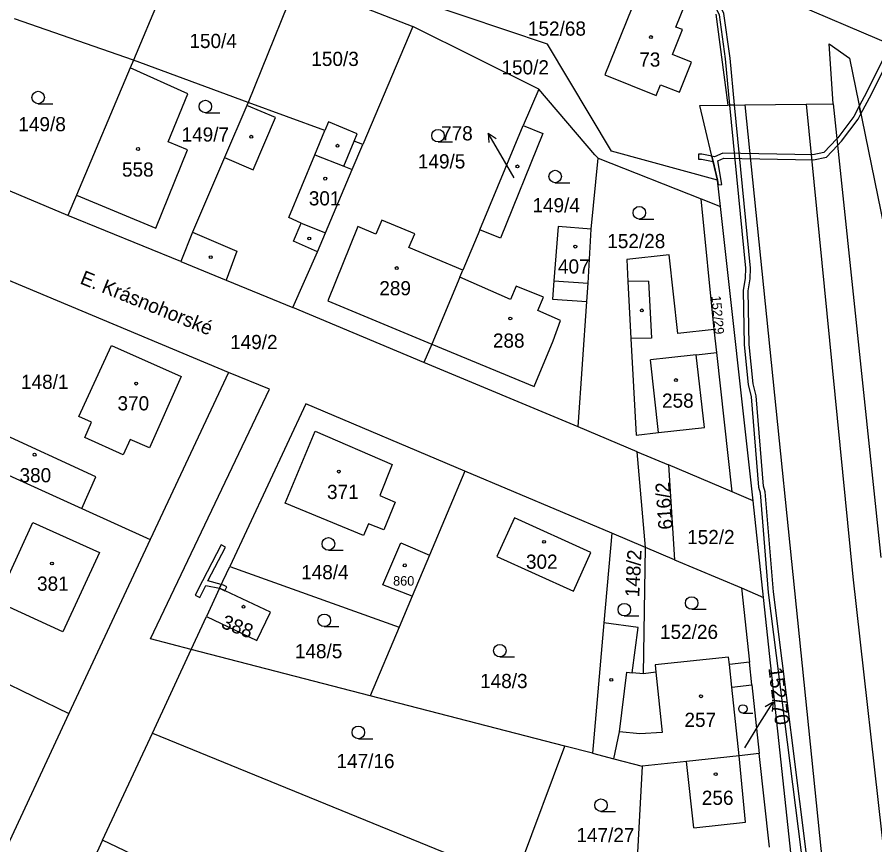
# Model space of a CAD drawing. Extents: x -783948 to -781889, y -1005870 to -1004430.
# Drawn here: x -783020.1 to -782917.3, y -1005140.8 to -1005041.6 of the extents above; entities that cross this region are included whole.
import ezdxf

# ---------------------------------------------------------------- set-up
doc = ezdxf.new("R2010")
doc.units = 0
for name, color, linetype in [('Vrstva 1', 7, 'Continuous'), ('Vrstva 13', 7, 'Continuous'), ('Vrstva 2', 7, 'Continuous'), ('Vrstva 3', 7, 'Continuous'), ('Vrstva 4', 7, 'Continuous'), ('Vrstva 5', 7, 'Continuous'), ('Vrstva 6', 7, 'Continuous'), ('Vrstva 7', 7, 'Continuous')]:
    doc.layers.add(name, color=color, linetype=linetype)

msp = doc.modelspace()

# ---------------------------------------------------------------- linework, layer by layer
at = {"layer": 'Vrstva 1'}
for p, q in [((-782999.94, -1005032.04), (-783006.14, -1005046.74)), ((-782986.5, -1005037.29), (-782972.67, -1005042.7)), ((-782987.66, -1005040.14), (-782992.39, -1005051.79)), ((-782936.33, -1005041.21), (-782934.89, -1005052.11)), ((-783006.14, -1005046.74), (-783020.39, -1005041.77)), ((-782972.67, -1005042.7), (-782978.65, -1005056.84)), ((-782957.57, -1005050.22), (-782972.67, -1005042.7)), ((-783006.51, -1005047.67), (-783012.96, -1005062.93)), ((-783006.14, -1005046.74), (-783006.51, -1005047.67)), ((-782999.61, -1005050.78), (-783006.51, -1005047.67)), ((-782992.39, -1005051.79), (-783006.14, -1005046.74)), ((-782957.57, -1005050.22), (-782959.43, -1005054.57)), ((-782922.29, -1005051.97), (-782916.56, -1005106.32)), ((-782979.31, -1005055.56), (-782982.78, -1005054.12)), ((-782964.62, -1005067.05), (-782959.43, -1005054.57)), ((-782959.43, -1005054.57), (-782957.07, -1005055.53)), ((-782957.07, -1005055.53), (-782962.16, -1005068.05)), ((-782951.29, -1005067), (-782950.45, -1005058.48)), ((-782950.45, -1005058.48), (-782938.09, -1005063.35)), ((-783013.98, -1005065.35), (-783027.87, -1005059.51)), ((-782935.79, -1005064.26), (-782936.14, -1005061.11)), ((-783012.96, -1005062.93), (-783013.98, -1005065.35)), ((-783012.96, -1005062.93), (-783003.45, -1005066.86)), ((-782938.09, -1005063.35), (-782935.79, -1005064.26)), ((-782936.55, -1005079.01), (-782938.09, -1005063.35)), ((-782931.85, -1005099.54), (-782935.79, -1005064.26)), ((-783000.45, -1005070.86), (-783013.98, -1005065.35)), ((-782964.62, -1005067.05), (-782966.68, -1005071.9)), ((-782962.16, -1005068.05), (-782964.62, -1005067.05)), ((-782951.29, -1005067), (-782955.25, -1005066.65)), ((-782951.64, -1005073.46), (-782951.29, -1005067)), ((-782966.68, -1005071.9), (-782973.12, -1005069.2)), ((-782967.02, -1005072.72), (-782966.68, -1005071.9)), ((-782994.76, -1005084.16), (-783021.91, -1005072.77)), ((-782967.02, -1005072.72), (-782970.39, -1005080.77)), ((-782960.94, -1005075.4), (-782967.02, -1005072.72)), ((-782951.79, -1005075.65), (-782951.64, -1005073.46)), ((-782971.34, -1005082.96), (-782987.02, -1005076.36)), ((-782982.85, -1005075.57), (-782970.39, -1005080.77)), ((-782952.82, -1005090.67), (-782951.79, -1005075.65)), ((-782936.24, -1005081.78), (-782936.55, -1005079.01)), ((-782970.39, -1005080.77), (-782971.34, -1005082.96)), ((-782934.38, -1005098.47), (-782936.24, -1005081.78)), ((-782952.82, -1005090.67), (-782971.34, -1005082.96)), ((-782994.76, -1005084.16), (-783004.12, -1005104.17)), ((-782945.78, -1005093.65), (-782952.82, -1005090.67)), ((-783010.64, -1005096.66), (-783022.7, -1005091.12)), ((-782945.78, -1005093.65), (-782942.02, -1005095.24)), ((-782944.78, -1005105.12), (-782945.78, -1005093.65)), ((-783024.44, -1005094.96), (-783012.33, -1005100.45)), ((-782966.41, -1005095.98), (-782970.66, -1005106.04)), ((-782948.82, -1005103.41), (-782966.41, -1005095.98)), ((-782934.38, -1005098.47), (-782942.02, -1005095.24)), ((-782942.02, -1005095.24), (-782941.29, -1005106.6)), ((-783012.33, -1005100.45), (-783010.64, -1005096.66)), ((-782931.85, -1005099.54), (-782934.38, -1005098.47)), ((-782930.61, -1005111.11), (-782931.85, -1005099.54)), ((-783012.33, -1005100.45), (-783004.12, -1005104.17)), ((-783004.12, -1005104.17), (-783013.87, -1005125.04)), ((-782948.82, -1005103.41), (-782949.77, -1005114.16)), ((-782944.78, -1005105.12), (-782948.82, -1005103.41)), ((-782944.99, -1005120.25), (-782944.78, -1005105.12)), ((-782941.29, -1005106.6), (-782944.78, -1005105.12)), ((-782970.66, -1005106.04), (-782972.74, -1005110.96)), ((-782941.29, -1005106.6), (-782933.28, -1005109.98)), ((-782995.82, -1005110), (-782994.6, -1005107.41)), ((-782994.6, -1005107.41), (-782974.31, -1005114.68)), ((-783044.29, -1005110.32), (-783013.87, -1005125.04)), ((-782995.82, -1005110), (-782997.38, -1005113.39)), ((-782989.73, -1005112.9), (-782995.82, -1005110)), ((-782933.28, -1005109.98), (-782930.61, -1005111.11)), ((-782933.28, -1005109.98), (-782932.32, -1005118.88)), ((-782972.74, -1005110.96), (-782974.31, -1005114.68)), ((-782914.35, -1005262.66), (-782930.61, -1005111.11)), ((-782999.22, -1005117.35), (-782997.38, -1005113.39)), ((-782997.38, -1005113.39), (-782991.34, -1005116.27)), ((-782991.34, -1005116.27), (-782989.73, -1005112.9)), ((-782949.77, -1005114.16), (-782951.14, -1005129.78)), ((-782945.66, -1005114.7), (-782949.77, -1005114.16)), ((-782974.31, -1005114.68), (-782977.78, -1005122.9)), ((-782946.36, -1005120.13), (-782945.66, -1005114.7)), ((-783003.87, -1005127.37), (-782999.22, -1005117.35)), ((-782977.78, -1005122.9), (-782999.22, -1005117.35)), ((-782934.81, -1005118.29), (-782943.63, -1005119.2)), ((-782932.03, -1005121.6), (-782932.32, -1005118.88)), ((-782944.99, -1005120.25), (-782946.36, -1005120.13)), ((-782932.03, -1005121.6), (-782931.14, -1005129.82)), ((-782954.45, -1005128.93), (-782977.78, -1005122.9)), ((-783013.87, -1005125.04), (-783023.28, -1005145.16)), ((-783009.84, -1005140.2), (-783003.87, -1005127.37)), ((-783003.87, -1005127.37), (-782960.46, -1005145.08)), ((-782960.46, -1005145.08), (-782954.45, -1005128.93)), ((-782951.14, -1005129.78), (-782954.45, -1005128.93)), ((-782931.14, -1005129.82), (-782933.54, -1005130.08)), ((-782929.92, -1005141.06), (-782931.14, -1005129.82)), ((-782945.15, -1005131.33), (-782946.27, -1005150.87)), ((-783009.84, -1005140.2), (-783017.65, -1005157)), ((-782947.58, -1005169.77), (-783009.84, -1005140.2))]:
    msp.add_line(p, q, dxfattribs=at)
for points in [[(-782936.14, -1005061.11), (-782948.86, -1005057.63), (-782956.51, -1005044.83), (-782971.51, -1005039.79)], [(-782943.48, -1005050.96), (-782942.96, -1005049.67), (-782940.7, -1005050.58), (-782939.25, -1005046.99), (-782941.54, -1005046.07), (-782940.33, -1005043.07), (-782941.12, -1005042.76), (-782939.93, -1005039.81)], [(-782946.4, -1005040.51), (-782949.63, -1005048.48), (-782943.48, -1005050.96)], [(-782922.29, -1005051.97), (-782922.75, -1005044.77), (-782920.33, -1005046.49), (-782913.56, -1005079.53)], [(-783003.45, -1005066.86), (-782999.67, -1005057.49), (-783001.99, -1005056.54), (-782999.61, -1005050.78)], [(-782950.45, -1005058.48), (-782950.85, -1005058.06), (-782957.57, -1005050.22)], [(-782992.39, -1005051.79), (-782992.55, -1005052.17), (-782995.23, -1005058.41), (-782999.06, -1005067.34), (-783000.45, -1005070.86)], [(-782982.78, -1005054.12), (-782983.21, -1005055.16), (-782992.39, -1005051.79)], [(-782936.14, -1005061.11), (-782938.26, -1005052.15), (-782934.89, -1005052.11)], [(-782934.89, -1005052.11), (-782932.86, -1005052.09), (-782925.51, -1005052.01), (-782922.29, -1005051.97)], [(-782978.65, -1005056.84), (-782979.68, -1005056.46), (-782979.31, -1005055.56)], [(-782987.02, -1005076.36), (-782984.09, -1005069.7), (-782983.13, -1005067.44), (-782979.92, -1005059.85), (-782978.65, -1005056.84)], [(-782973.12, -1005069.2), (-782972.43, -1005067.55), (-782976.38, -1005065.9), (-782977.08, -1005067.58), (-782979.23, -1005066.68), (-782982.85, -1005075.57)], [(-782955.25, -1005066.65), (-782955.76, -1005073.17), (-782955.93, -1005075.36), (-782951.79, -1005075.65)], [(-782936.55, -1005079.01), (-782940.89, -1005079.49), (-782941.94, -1005070.06), (-782947.02, -1005070.63), (-782946.88, -1005073.27), (-782946.51, -1005080.1), (-782945.89, -1005091.67), (-782943.22, -1005091.37), (-782937.71, -1005090.76), (-782938.68, -1005082.05), (-782936.24, -1005081.78)], [(-783000.45, -1005070.86), (-782995.02, -1005073.1), (-782987.02, -1005076.36)], [(-782954.94, -1005077.92), (-782957.67, -1005076.74), (-782956.99, -1005075.15), (-782960.27, -1005073.8), (-782960.94, -1005075.4)], [(-782970.39, -1005080.77), (-782958.13, -1005085.84), (-782955.85, -1005080.35), (-782954.94, -1005077.92)], [(-783004.23, -1005093.2), (-783006.53, -1005092.2), (-783007.35, -1005094.03), (-783011.98, -1005091.94), (-783011.16, -1005090.11), (-783012.69, -1005089.44), (-783008.76, -1005080.91), (-783000.42, -1005084.65), (-783004.23, -1005093.2)], [(-782999.22, -1005117.35), (-783004.1, -1005116.09), (-782989.84, -1005086.15), (-782994.76, -1005084.16)], [(-782966.41, -1005095.98), (-782985.47, -1005087.93), (-782994.6, -1005107.41)], [(-782984.37, -1005091.2), (-782975.12, -1005095.2), (-782976.59, -1005098.92), (-782974.78, -1005099.68), (-782976.14, -1005103.03), (-782977.95, -1005102.28), (-782978.55, -1005103.71), (-782987.96, -1005099.8), (-782984.37, -1005091.2)], [(-783018.2, -1005102.12), (-783010.19, -1005105.74), (-783014.61, -1005115.24), (-783022.55, -1005111.59), (-783018.2, -1005102.12)], [(-782953.4, -1005110.35), (-782951.31, -1005105.72), (-782960.48, -1005101.58), (-782962.57, -1005106.21), (-782953.4, -1005110.35)], [(-782972.74, -1005110.96), (-782976.24, -1005109.61), (-782974.08, -1005104.56), (-782970.66, -1005106.04)], [(-782932.32, -1005118.88), (-782934.72, -1005119.14), (-782934.81, -1005118.29)], [(-782943.63, -1005119.2), (-782943.54, -1005120.09), (-782944.99, -1005120.25)], [(-782933.54, -1005130.08), (-782934.43, -1005121.86), (-782932.03, -1005121.6)], [(-782951.14, -1005129.78), (-782948.55, -1005130.45), (-782945.15, -1005131.33)], [(-782933.54, -1005130.08), (-782939.84, -1005130.76), (-782945.15, -1005131.33)]]:
    msp.add_lwpolyline(points, dxfattribs=at)
at = {"layer": 'Vrstva 13'}
for points in [[(-782940.02, -1005021.84), (-782939.29, -1005027.27), (-782940.33, -1005028.2), (-782942.46, -1005036.39), (-782938.04, -1005038.43), (-782936.61, -1005039.91), (-782935.96, -1005041.32), (-782935.24, -1005046.58), (-782934.7, -1005052.11), (-782934.09, -1005052.1), (-782934.64, -1005046.5), (-782935.38, -1005041.16), (-782936.11, -1005039.57), (-782937.68, -1005037.93), (-782941.76, -1005036.05), (-782939.79, -1005028.48), (-782938.7, -1005027.41), (-782939.13, -1005023.32), (-782939.31, -1005021.83)], [(-782919.15, -1005052.25), (-782918.96, -1005053.18), (-782917.69, -1005050.8), (-782911.18, -1005037.68), (-782908.96, -1005033.22), (-782913.6, -1005031.23), (-782914.81, -1005031.46), (-782914.06, -1005031.69), (-782909.78, -1005033.52), (-782911.73, -1005037.44), (-782918.23, -1005050.53)], [(-782935.39, -1005058.48), (-782924.64, -1005058.69), (-782923.08, -1005058.35), (-782921.76, -1005056.96), (-782921.27, -1005056.43), (-782919.29, -1005053.79), (-782918.96, -1005053.18), (-782919.15, -1005052.25), (-782919.8, -1005053.47), (-782921.73, -1005056.05), (-782921.85, -1005056.17), (-782923.38, -1005057.8), (-782924.7, -1005058.09), (-782935.51, -1005057.88), (-782936.49, -1005058.3), (-782936.82, -1005058.23), (-782936.67, -1005058.87), (-782936.14, -1005061.11), (-782936.08, -1005061.69), (-782935.63, -1005061.63), (-782936.09, -1005058.78)], [(-782936.67, -1005058.87), (-782936.82, -1005058.23), (-782938.03, -1005058), (-782938.43, -1005058.01), (-782938.4, -1005058.61), (-782938.07, -1005058.6)], [(-782995.62, -1005109.58), (-782997.22, -1005109.13), (-782995.09, -1005105.11), (-782995.63, -1005104.83), (-782997.88, -1005109.11), (-782998.72, -1005110.85), (-782998.18, -1005111.11), (-782997.46, -1005109.68), (-782995.82, -1005110)], [(-782995.82, -1005110), (-782995.17, -1005110.31), (-782994.96, -1005109.83), (-782995.36, -1005109.65), (-782995.62, -1005109.58)]]:
    msp.add_lwpolyline(points, close=True, dxfattribs=at)
msp.add_lwpolyline([(-782925.23, -1005143.83), (-782929.45, -1005110.46), (-782930.41, -1005098.47), (-782930.64, -1005097.77), (-782931.49, -1005086.97), (-782931.87, -1005085.5), (-782932.36, -1005080.81), (-782932.48, -1005074.36), (-782932.21, -1005072.92), (-782932.18, -1005071.65), (-782934.09, -1005052.1), (-782934.7, -1005052.11), (-782932.78, -1005071.67), (-782932.81, -1005072.86), (-782933.08, -1005074.32), (-782932.96, -1005080.85), (-782932.47, -1005085.6), (-782932.09, -1005087.07), (-782931.24, -1005097.89), (-782931.01, -1005098.59), (-782930.05, -1005110.52), (-782925.83, -1005143.89)], dxfattribs=at)
at = {"layer": 'Vrstva 3'}
for p, q in [((-783017.55, -1005051.96), (-783015.8, -1005051.96)), ((-782997.52, -1005053.04), (-782995.77, -1005053.04)), ((-782969.63, -1005056.53), (-782967.88, -1005056.53)), ((-782955.59, -1005061.42), (-782953.84, -1005061.42)), ((-782945.51, -1005065.77), (-782943.76, -1005065.77)), ((-782982.77, -1005105.45), (-782981.02, -1005105.45)), ((-782947.31, -1005113.33), (-782945.56, -1005113.33)), ((-782939.23, -1005112.54), (-782937.48, -1005112.54)), ((-782983.27, -1005114.61), (-782981.52, -1005114.61)), ((-782962.22, -1005118.25), (-782960.47, -1005118.25)), ((-782933.09, -1005124.97), (-782931.92, -1005124.97)), ((-782979.18, -1005128.04), (-782977.43, -1005128.04)), ((-782950.11, -1005136.76), (-782948.36, -1005136.76))]:
    msp.add_line(p, q, dxfattribs=at)
for centre, radius in [((-783017.55, -1005051.21), 0.75), ((-782997.52, -1005052.29), 0.75), ((-782969.63, -1005055.78), 0.75), ((-782955.59, -1005060.67), 0.75), ((-782945.51, -1005065.02), 0.75), ((-782982.77, -1005104.7), 0.75), ((-782939.23, -1005111.79), 0.75), ((-782947.31, -1005112.58), 0.75), ((-782983.27, -1005113.86), 0.75), ((-782962.22, -1005117.5), 0.75), ((-782933.1, -1005124.47), 0.502), ((-782979.18, -1005127.29), 0.75), ((-782950.11, -1005136.01), 0.75)]:
    msp.add_circle(centre, radius, dxfattribs=at)
at = {"layer": 'Vrstva 4'}
for p, q in [((-782989.12, -1005053.62), (-782992.55, -1005052.17)), ((-782932.86, -1005052.09), (-782921.8, -1005160.42)), ((-782925.51, -1005052.01), (-782919.91, -1005108.66)), ((-782991.77, -1005059.89), (-782989.12, -1005053.62)), ((-782984.41, -1005058.06), (-782983.21, -1005055.16)), ((-782980.93, -1005059.45), (-782979.68, -1005056.46)), ((-782995.23, -1005058.41), (-782991.77, -1005059.89)), ((-782987.52, -1005065.57), (-782984.41, -1005058.06)), ((-782984.41, -1005058.06), (-782980.93, -1005059.45)), ((-782980.93, -1005059.45), (-782979.92, -1005059.85)), ((-782986.03, -1005066.28), (-782987.52, -1005065.57)), ((-782986.97, -1005068.44), (-782986.03, -1005066.28)), ((-782986.03, -1005066.28), (-782983.13, -1005067.44)), ((-782999.06, -1005067.34), (-782993.76, -1005069.62)), ((-782984.09, -1005069.7), (-782986.97, -1005068.44)), ((-782993.76, -1005069.62), (-782995.02, -1005073.1)), ((-782955.76, -1005073.17), (-782951.64, -1005073.46)), ((-782944.42, -1005073.23), (-782946.88, -1005073.27)), ((-782944.42, -1005073.23), (-782944.05, -1005080.06)), ((-782944.05, -1005080.06), (-782946.51, -1005080.1)), ((-782941.99, -1005082.42), (-782944.19, -1005082.66)), ((-782938.68, -1005082.05), (-782941.99, -1005082.42)), ((-782943.22, -1005091.37), (-782944.19, -1005082.66)), ((-782919.91, -1005108.66), (-782904.65, -1005244.68)), ((-782934.43, -1005121.86), (-782934.72, -1005119.14)), ((-782947.89, -1005127.23), (-782947.01, -1005120.08)), ((-782947.01, -1005120.08), (-782946.36, -1005120.13)), ((-782943.54, -1005120.09), (-782942.78, -1005127.29)), ((-782948.55, -1005130.45), (-782947.89, -1005127.23)), ((-782945.43, -1005127.44), (-782947.89, -1005127.23)), ((-782942.78, -1005127.29), (-782945.43, -1005127.44)), ((-782938.98, -1005138.72), (-782939.84, -1005130.76)), ((-782932.79, -1005138.05), (-782933.54, -1005130.08)), ((-782938.98, -1005138.72), (-782932.79, -1005138.05))]:
    msp.add_line(p, q, dxfattribs=at)
at = {"layer": 'Vrstva 5'}
for centre in [(-782944.12, -1005043.97), (-782992.02, -1005055.91), (-782981.68, -1005056.99), (-783005.59, -1005057.38), (-782960.12, -1005059.47), (-782983.15, -1005060.93), (-782985.07, -1005068.1), (-782953.18, -1005069.07), (-782996.87, -1005070.34), (-782974.58, -1005071.65), (-782945.21, -1005076.72), (-782960.97, -1005077.69), (-783005.81, -1005085.49), (-782941.12, -1005085.07), (-783017.98, -1005094.01), (-782981.52, -1005096.03), (-782956.93, -1005104.45), (-783015.91, -1005107.05), (-782973.62, -1005107.27), (-782992.95, -1005112.23), (-782948.87, -1005120.99), (-782938.12, -1005122.96), (-782936.36, -1005132.29)]:
    msp.add_circle(centre, 0.175, dxfattribs=at)
at = {"layer": 'Vrstva 6'}
msp.add_line((-783060.19, -1004982.81), (-782841.72, -1005076.44), dxfattribs=at)
at = {"layer": 'Vrstva 7'}
for p, q in [((-782962.11, -1005058.09), (-782963.61, -1005055.49)), ((-782963.61, -1005055.49), (-782962.68, -1005056.11)), ((-782963.61, -1005055.49), (-782963.54, -1005056.61)), ((-782960.52, -1005060.82), (-782962.11, -1005058.09)), ((-782931.05, -1005126.2), (-782929.46, -1005123.66)), ((-782929.46, -1005123.66), (-782930.42, -1005124.24)), ((-782929.46, -1005123.66), (-782929.57, -1005124.77)), ((-782932.86, -1005129.12), (-782931.05, -1005126.2))]:
    msp.add_line(p, q, dxfattribs=at)

# ---------------------------------------------------------------- texts
at = {"layer": 'Vrstva 2'}
for s, height, p in [('152/68', 1.7, (-782958.86, -1005043.8)), ('150/4', 1.7, (-782999.43, -1005045.28)), ('150/3', 1.7, (-782984.82, -1005047.43)), ('150/2', 1.7, (-782962.03, -1005048.44)), ('73', 1.7, (-782945.52, -1005047.51)), ('149/8', 1.7, (-783019.93, -1005055.25)), ('149/7', 1.7, (-783000.37, -1005056.49)), ('778', 1.7, (-782969.27, -1005056.35)), ('149/5', 1.7, (-782972.05, -1005059.71)), ('558', 1.7, (-783007.51, -1005060.69)), ('301', 1.7, (-782985.12, -1005064.14)), ('149/4', 1.7, (-782958.32, -1005064.97)), ('152/28', 1.7, (-782949.35, -1005069.26)), ('407', 1.7, (-782955.26, -1005072.3)), ('289', 1.7, (-782976.67, -1005074.91)), ('288', 1.7, (-782963.06, -1005081.19)), ('149/2', 1.7, (-782994.55, -1005081.36)), ('148/1', 1.7, (-783019.61, -1005086.13)), ('258', 1.7, (-782942.79, -1005088.38)), ('370', 1.7, (-783008.05, -1005088.7)), ('380', 1.7, (-783019.79, -1005097.32)), ('371', 1.7, (-782982.94, -1005099.32)), ('152/2', 1.7, (-782939.78, -1005104.73)), ('302', 1.7, (-782959.1, -1005107.68)), ('148/4', 1.7, (-782986.04, -1005108.94)), ('381', 1.7, (-783017.69, -1005110.31)), ('860', 1.139, (-782975.02, -1005109.7)), ('152/26', 1.7, (-782943.03, -1005116.09)), ('148/5', 1.7, (-782986.79, -1005118.4)), ('148/3', 1.7, (-782964.59, -1005121.98)), ('257', 1.7, (-782940.1, -1005126.63)), ('147/16', 1.7, (-782981.8, -1005131.57)), ('256', 1.7, (-782938.02, -1005135.97)), ('147/27', 1.7, (-782953.05, -1005140.44))]:
    msp.add_text(s, height=height, dxfattribs=at).set_placement(p)
for s, height, rotation, p in [('152/29', 1.14, 275, (-782936.88, -1005074.99)), ('616/2', 1.7, 94, (-782941.51, -1005102.93)), ('148/2', 1.7, 87, (-782945.53, -1005111.12)), ('388', 1.7, 339, (-782995.74, -1005114.71)), ('152/70', 1.7, 277, (-782930.05, -1005119.58))]:
    msp.add_text(s, height=height, rotation=rotation, dxfattribs=at).set_placement(p)
at = {"layer": 'Vrstva 7'}
msp.add_text('E. Krásnohorské', height=1.7, rotation=338, dxfattribs=at).set_placement((-783012.65, -1005073.46))

doc.saveas('drawing.dxf')
